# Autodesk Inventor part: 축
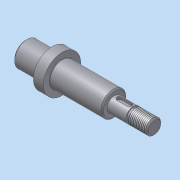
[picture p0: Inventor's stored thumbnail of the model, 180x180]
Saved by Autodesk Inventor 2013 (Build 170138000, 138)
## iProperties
Created: 2015-03
Part Number: 축
Material: 강
Document SubType Name: Modeling
Designer: KYOUNG IL JANG
Density: 1 g/cm^3
CustomPartVersion: 1
Author: KYOUNG IL JANG
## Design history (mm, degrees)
sketch "스케치5"
  geometry: L1 (0, 0)-(103, 0); L2 (0, 0)-(103, 0); L3 (103, 0)-(103, 6); L4 (71, 6)-(71, 10); L5 (71, 10)-(29, 10); L6 (29, 10)-(29, 15); L7 (29, 15)-(21, 15); L8 (21, 15)-(21, 10); L9 (21, 10)-(0, 10); L10 (0, 10)-(0, 0); L11 (86, 6)-(86, 5); L12 (86, 5)-(88, 5); L13 (88, 5)-(88, 6); L14 (103, 6)-(88, 6); L15 (86, 6)-(71, 6)
  constraints: 31 end point, 12 perpendicular, 9 parallel, 1 collinear, 1 horizontal
  dimensions: "d43" = 20 diameter of L9 L1; "d44" = 30 diameter of L7 L1; "d45" = 20 diameter of L5 L2; "d47" = 8 distance of L6.end L7.end; "d48" = 32 distance between parallel lines of L3 L4; "d49" = 42 distance between parallel lines of L4 L6; "d50" = 21 distance of L8.end L9.end; "d52" = 12 diameter of L14 L1; "d53" = 15 distance between parallel lines of L3 L13; "d54" = 2 distance of L11.end L12.end; "d55" = 1 distance between parallel lines of L14 L12
revolve "회전4" sketch "스케치5" stored, may be unused: angle "d51" = 90 deg
feature "스레드6" dims "d56" = 10, "d57" = 0
chamfer "모따기6" distance "d32" = 1; stored, may be unused: second distance "d33" = 0.4, angle "d34" = 45 deg
chamfer "모따기5" distance "d27" = 1; stored, may be unused: second distance "d28" = 0.125, angle "d29" = 45 deg
fillet "모깎기1" dims "d17" = 0.3
fillet "모깎기2" dims "d18" = 0.3
chamfer "모따기3" distance "d19" = 1; stored, may be unused: second distance "d20" = 1, angle "d21" = 45 deg
node "작업 평면1"
sketch "스케치6"
  geometry: L1 (-3.5, 2)-(4.5, 2); L2 (4.5, -2)-(-3.5, -2); L3 (-7.5, 9)-(-7.5, -9) reference; A1 r 2 centre (4.5, 0) between (4.5, -2) and (4.5, 2); A2 r 2 centre (-3.5, 0) between (-3.5, 2) and (-3.5, -2); 1 further point
  constraints: 4 end point, 4 point on circle, 4 tangent, 2 centre point, 1 horizontal, 1 horizontal alignment, 1 parallel
  dimensions: "d59" = 2 distance edge to line of A2 L3; "d60" = 12 dimension on A1 A2; "d61" = 4 distance between parallel lines of L2 L1
extrude "돌출1" cut sketch "스케치6" distance "d62" = 2.3; taper "d63" = 0 deg
node "솔리드1"
node "솔리드2"
other parameters: "d46" = 12
